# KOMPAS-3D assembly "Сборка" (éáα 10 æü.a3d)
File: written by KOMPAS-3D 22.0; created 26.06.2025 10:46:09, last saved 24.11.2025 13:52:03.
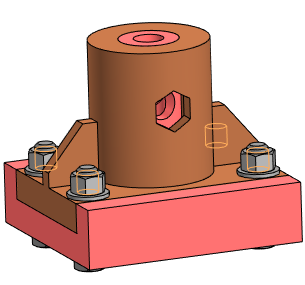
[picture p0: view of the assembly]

Document properties: Автор: Helen; Полное имя файла: C:\Для ноута\Инженерная графика\ППЭ 2025-2026\Варианты 1-38\Вариант 10 СБ\Вар 10 СБ\Вар 10 СБ.a3d

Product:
- Component [detail]: Сборка  | qty 4  | Масса: 0.008612; source file: ..\..\Вариант 8 СБ\Вар 8 СБ\Шайба 14.m3d
- Component [detail]: Сборка  | qty 4  | Масса: 0.02533; source file: ..\..\Вариант 8 СБ\Вар 8 СБ\Гайка М14.m3d
- Component [detail]: Болт М14x60 ГОСТ 15591-70  | qty 4  | Масса: 0.091885; source file: ..\..\Вариант 8 СБ\Вар 8 СБ\Болт М14x60 ГОСТ 15591-70.m3d
- Component [detail]: Основание  | designation Вариант 10  | qty 1  | Масса: 4.843282; source file: Основание вар 10.m3d
- Component [detail]: Nodes  | qty 1  | Масса: 4.30212; source file: Корпус вар 10.m3d
- Part/product: Сборка
    Масса: 9.648709

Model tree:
1. Массив по сетке:1  (with: Элемент выдавливания:5, Операция без истории:1, Элемент выдавливания:1)  (4 pattern instances)
     Шаг 1 = 120; Угол раствора = 90; Шаг 2 = 70

Referenced files in C:\Для ноута\Инженерная графика\ППЭ 2025-2026\Варианты 1-38\Вариант 10 СБ\Вар 10 СБ\: Основание вар 10.m3d, Корпус вар 10.m3d
Referenced files in C:\Для ноута\Инженерная графика\ППЭ 2025-2026\Варианты 1-38\Вариант 8 СБ\Вар 8 СБ\: Шайба 14.m3d, Гайка М14.m3d, Болт М14x60 ГОСТ 15591-70.m3d
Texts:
  Сборка (1)
  Болт М14x60 ГОСТ 15591-70 (1)
  Вариант 10 Основание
